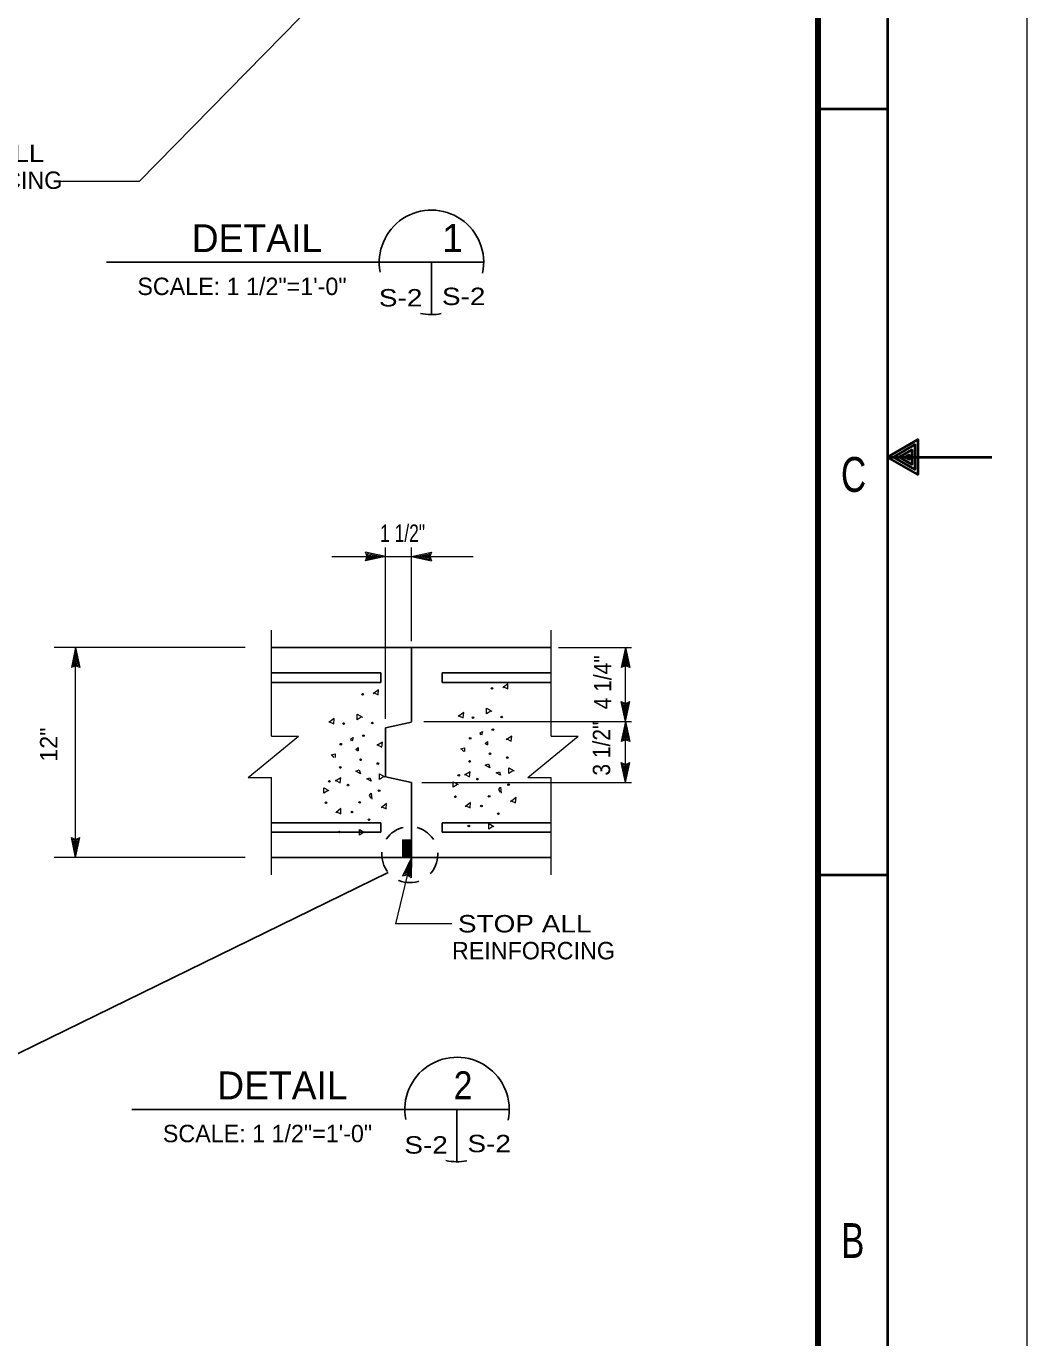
# Model space of a CAD drawing. Extents: x -22.3 to 19.7, y -11.8 to 18.2.
# Drawn here: x 12.51 to 19.69, y -3.16 to 6.25 of the extents above; entities that cross this region are included whole.
import ezdxf
from ezdxf.enums import TextEntityAlignment as Align

# ---------------------------------------------------------------- set-up
doc = ezdxf.new("R2010")
doc.units = 0
doc.header["$LTSCALE"] = 0.05
doc.linetypes.add('MEDIUM_DASHED', pattern=[4.5, 3, -1.5])
doc.layers.add('1', color=7, linetype='Continuous', lineweight=13)
doc.layers.add('2', color=7, linetype='Continuous', lineweight=13)

msp = doc.modelspace()

# ---------------------------------------------------------------- linework, layer by layer
at = {"layer": '1', "lineweight": 40}
for p, q in [((18.19058, 5.66031), (18.69058, 5.66031)), ((18.69058, 3.16031), (19.44058, 3.16031)), ((18.19058, 0.16031), (18.69058, 0.16031))]:
    msp.add_line(p, q, dxfattribs=at)
at = {"layer": '1', "lineweight": 25}
for p, q in [((13.08258, 4.55831), (15.79158, 4.55831)), ((15.41658, 4.55831), (15.41658, 4.18331)), ((14.26858, 1.79231), (16.27658, 1.79231)), ((15.27258, 1.26131), (15.27258, 1.79231)), ((15.05158, 1.61231), (14.27058, 1.61231)), ((15.05158, 1.54131), (15.05158, 1.61231)), ((15.49358, 1.61231), (16.27458, 1.61231)), ((15.49358, 1.54131), (15.49358, 1.61231)), ((15.05158, 1.54131), (14.27058, 1.54131)), ((15.49358, 1.54131), (16.27458, 1.54131)), ((15.27358, 1.25631), (15.08558, 1.21631)), ((15.08558, 0.86331), (15.08558, 1.21631)), ((15.27258, 0.82331), (15.08558, 0.86331)), ((15.27258, 0.28531), (15.27258, 0.82331)), ((15.05158, 0.53331), (14.26858, 0.53331)), ((15.05158, 0.46731), (15.05158, 0.53331)), ((15.49358, 0.53331), (16.27658, 0.53331)), ((15.49358, 0.46731), (15.49358, 0.53331)), ((15.05158, 0.46731), (14.26858, 0.46731)), ((15.21658, 0.28531), (15.21658, 0.41031)), ((15.22258, 0.28531), (15.22258, 0.41031)), ((15.22858, 0.28531), (15.22858, 0.41031)), ((15.23458, 0.28531), (15.23458, 0.41031)), ((15.23958, 0.28531), (15.23958, 0.41031)), ((15.24458, 0.28531), (15.24458, 0.41031)), ((15.25058, 0.28531), (15.25058, 0.41031)), ((15.25558, 0.28531), (15.25558, 0.41031)), ((15.26058, 0.28531), (15.26058, 0.41031)), ((15.26558, 0.28531), (15.26558, 0.41031)), ((15.26958, 0.28531), (15.26958, 0.41031)), ((15.49358, 0.46731), (16.27658, 0.46731)), ((14.26858, 0.28531), (16.27658, 0.28531)), ((13.26558, -1.52369), (15.97458, -1.52369)), ((15.59958, -1.52369), (15.59958, -1.89869))]:
    msp.add_line(p, q, dxfattribs=at)
at = {"layer": '1'}
for p, q in [((15.08558, 2.44531), (14.94158, 2.47631)), ((15.04858, 2.44531), (14.95458, 2.46531)), ((14.96358, 2.44531), (14.95458, 2.46531)), ((15.01258, 2.44531), (14.96758, 2.45431)), ((14.97158, 2.44531), (14.96758, 2.45431)), ((15.08558, 1.28031), (15.08558, 2.51131)), ((15.27258, 1.83731), (15.27258, 2.51131)), ((15.27358, 2.44531), (15.41758, 2.47631)), ((15.31058, 2.44531), (15.40458, 2.46531)), ((15.34658, 2.44531), (15.39158, 2.45531)), ((15.39158, 2.45531), (15.38758, 2.44531)), ((15.40458, 2.46531), (15.39558, 2.44531)), ((15.08558, 2.44531), (14.94158, 2.41431)), ((15.04858, 2.44531), (14.95458, 2.42531)), ((14.95458, 2.42531), (14.96358, 2.44531)), ((15.01258, 2.44531), (14.96758, 2.43531)), ((14.96758, 2.43531), (14.97158, 2.44531)), ((15.27358, 2.44531), (15.41758, 2.41431)), ((15.31058, 2.44531), (15.40458, 2.42531)), ((15.34658, 2.44531), (15.39158, 2.43631)), ((15.38758, 2.44531), (15.39158, 2.43631)), ((15.39558, 2.44531), (15.40458, 2.42531)), ((14.26858, 1.15731), (14.26858, 1.91831)), ((16.27658, 1.15731), (16.27658, 1.91831)), ((14.07758, 1.79231), (12.70658, 1.79231)), ((12.86158, 1.79231), (12.83058, 1.64831)), ((12.86158, 0.28531), (12.86158, 1.79231)), ((12.86158, 1.79231), (12.89258, 1.64831)), ((16.32858, 1.79231), (16.85258, 1.79231)), ((16.80958, 1.79231), (16.77858, 1.64831)), ((16.80958, 1.79231), (16.84058, 1.64831)), ((12.86158, 1.75531), (12.84158, 1.66131)), ((12.86158, 1.71931), (12.85258, 1.67431)), ((12.86158, 1.75531), (12.88158, 1.66131)), ((12.86158, 1.71931), (12.87158, 1.67431)), ((16.80958, 1.75531), (16.78958, 1.66131)), ((16.80958, 1.71931), (16.80058, 1.67431)), ((16.80958, 1.75531), (16.82958, 1.66131)), ((16.80958, 1.71931), (16.81958, 1.67431)), ((12.86158, 1.67031), (12.84158, 1.66131)), ((12.86158, 1.67831), (12.85258, 1.67431)), ((12.87158, 1.67431), (12.86158, 1.67831)), ((12.88158, 1.66131), (12.86158, 1.67031)), ((16.80958, 1.67031), (16.78958, 1.66131)), ((16.80958, 1.67831), (16.80058, 1.67431)), ((16.81958, 1.67431), (16.80958, 1.67831)), ((16.82958, 1.66131), (16.80958, 1.67031)), ((16.80958, 1.26131), (16.77858, 1.40531)), ((16.80958, 1.29831), (16.78958, 1.39231)), ((16.78958, 1.39231), (16.80958, 1.38331)), ((16.80958, 1.33431), (16.79958, 1.37931)), ((16.79958, 1.37931), (16.80958, 1.37531)), ((16.80958, 1.26131), (16.84058, 1.40531)), ((16.80958, 1.29831), (16.82958, 1.39231)), ((16.80958, 1.38331), (16.82958, 1.39231)), ((16.80958, 1.33431), (16.81858, 1.37931)), ((16.80958, 1.37531), (16.81858, 1.37931)), ((15.36158, 1.26131), (16.85258, 1.26131)), ((16.80958, 1.26131), (16.77858, 1.11731)), ((16.80958, 1.22431), (16.78958, 1.13031)), ((16.80958, 1.26131), (16.84058, 1.11731)), ((16.80958, 1.22431), (16.82958, 1.13031)), ((14.10058, 0.86031), (14.46158, 1.15731)), ((14.26858, 1.15731), (14.46158, 1.15731)), ((16.10858, 0.86031), (16.46958, 1.15731)), ((16.27658, 1.15731), (16.46958, 1.15731)), ((16.80958, 1.13931), (16.78958, 1.13031)), ((16.80958, 1.18831), (16.80058, 1.14331)), ((16.80958, 1.14731), (16.80058, 1.14331)), ((16.80958, 1.18831), (16.81958, 1.14331)), ((16.81958, 1.14331), (16.80958, 1.14731)), ((16.82958, 1.13031), (16.80958, 1.13931)), ((16.80958, 0.82331), (16.77858, 0.96731)), ((16.80958, 0.86031), (16.78958, 0.95431)), ((16.78958, 0.95431), (16.80958, 0.94531)), ((16.80958, 0.82331), (16.84058, 0.96731)), ((16.80958, 0.86031), (16.82958, 0.95431)), ((16.80958, 0.94531), (16.82958, 0.95431)), ((14.10058, 0.86031), (14.26858, 0.86031)), ((14.26858, 0.16131), (14.26858, 0.86031)), ((16.10858, 0.86031), (16.27658, 0.86031)), ((16.27658, 0.16131), (16.27658, 0.86031)), ((16.80958, 0.89631), (16.79958, 0.94131)), ((16.79958, 0.94131), (16.80958, 0.93731)), ((16.80958, 0.89631), (16.81858, 0.94131)), ((16.80958, 0.93731), (16.81858, 0.94131)), ((15.34658, 0.82331), (16.85258, 0.82331)), ((12.86158, 0.28531), (12.83058, 0.42931)), ((12.86158, 0.32231), (12.84158, 0.41631)), ((12.84158, 0.41631), (12.86158, 0.40731)), ((12.86158, 0.35831), (12.85158, 0.40331)), ((12.85158, 0.40331), (12.86158, 0.39931)), ((12.86158, 0.28531), (12.89258, 0.42931)), ((12.86158, 0.32231), (12.88158, 0.41631)), ((12.86158, 0.40731), (12.88158, 0.41631)), ((12.86158, 0.35831), (12.87058, 0.40331)), ((12.86158, 0.39931), (12.87058, 0.40331)), ((14.07758, 0.28531), (12.70658, 0.28531)), ((15.27258, 0.28531), (15.15858, -0.19069)), ((15.27258, 0.28531), (15.20858, 0.15231)), ((15.27258, 0.28531), (15.26958, 0.13831)), ((15.26358, 0.24931), (15.22258, 0.16231)), ((15.25558, 0.21431), (15.23658, 0.17231)), ((15.25558, 0.21431), (15.25458, 0.16831)), ((15.26358, 0.24931), (15.26158, 0.15331)), ((15.24458, 0.16631), (15.22258, 0.16231)), ((15.24558, 0.17431), (15.23658, 0.17231)), ((15.26158, 0.15331), (15.24458, 0.16631)), ((15.25458, 0.16831), (15.24558, 0.17431)), ((15.56158, -0.19069), (15.15858, -0.19069))]:
    msp.add_line(p, q, dxfattribs=at)
for points in [[(-22.30942, 18.16031), (19.69058, 18.16031), (19.69058, -11.83969)], [(14.60258, 6.44931), (13.31658, 5.13931), (12.74958, 5.13931)], [(14.94158, 2.41431), (14.95558, 2.44531), (14.94158, 2.47631)], [(15.41758, 2.47631), (15.40358, 2.44531), (15.41758, 2.41431)], [(14.70058, 2.44531), (15.08558, 2.44531), (15.27358, 2.44531), (15.71658, 2.44531)], [(16.80958, 0.82331), (16.80958, 1.26131), (16.80958, 1.79231)], [(12.89258, 1.64831), (12.86158, 1.66231), (12.83058, 1.64831)], [(16.84058, 1.64831), (16.80958, 1.66231), (16.77858, 1.64831)], [(16.77858, 1.40531), (16.80958, 1.39131), (16.84058, 1.40531)], [(16.84058, 1.11731), (16.80958, 1.13131), (16.77858, 1.11731)], [(16.77858, 0.96731), (16.80958, 0.95331), (16.84058, 0.96731)], [(12.83058, 0.42931), (12.86158, 0.41531), (12.89258, 0.42931)], [(15.26958, 0.13831), (15.24258, 0.15931), (15.20858, 0.15231)]]:
    msp.add_lwpolyline(points, dxfattribs=at)
at = {"layer": '1', "lineweight": 40}
for points in [[(-21.30942, -10.83969), (-21.30942, 17.16031), (18.69058, 17.16031), (18.69058, -10.83969)], [(18.69058, 3.16031), (18.90758, 3.28531), (18.90758, 3.03531)]]:
    msp.add_lwpolyline(points, close=True, dxfattribs=at)
at = {"layer": '1', "lineweight": 90}
msp.add_lwpolyline([(-19.80942, 16.66031), (18.19058, 16.66031), (18.19058, -10.33969), (-19.80942, -10.33969)], close=True, dxfattribs=at)
at = {"layer": '1', "lineweight": 40}
for points in [[(18.73358, 3.16031), (18.88658, 3.24931), (18.88658, 3.07131), (18.73458, 3.15931)], [(18.77358, 3.15931), (18.86558, 3.21331), (18.86558, 3.10731), (18.77258, 3.16131)], [(18.81558, 3.15931), (18.84558, 3.17731), (18.84558, 3.14331), (18.81858, 3.15831)]]:
    msp.add_lwpolyline(points, dxfattribs=at)
at = {"layer": '1', "lineweight": 25}
for points in [[(15.21058, 0.28531), (15.21058, 0.41031), (15.27258, 0.41031)], [(15.10558, 0.17831), (12.12358, -1.28069), (12.35458, -1.09869)]]:
    msp.add_lwpolyline(points, dxfattribs=at)
at = {"layer": '1', "linetype": 'MEDIUM_DASHED', "lineweight": 25}
msp.add_circle((15.26058, 0.30631), 0.20112, dxfattribs=at)
at = {"layer": '1', "lineweight": 25}
for centre, start, end in [((15.41658, 4.55831), 348.02387, 190.92017), ((15.41658, 4.55831), 257.81974, 280.71312), ((15.59958, -1.52369), 348.02387, 190.92017), ((15.59958, -1.52369), 257.81974, 280.71312)]:
    msp.add_arc(centre, 0.375, start, end, dxfattribs=at)
at = {"layer": '2'}
for p, q in [((15.64758, 1.04531), (15.62958, 1.06531)), ((14.71858, 1.00231), (14.70058, 1.02231))]:
    msp.add_line(p, q, dxfattribs=at)
for points in [[(15.92758, 1.51331), (15.96358, 1.49531), (15.96558, 1.53131), (15.92758, 1.50331)], [(14.99858, 1.47031), (15.03458, 1.45231), (15.03658, 1.48831), (14.99858, 1.46031)], [(15.60758, 1.30531), (15.64358, 1.28731), (15.64758, 1.32531), (15.60758, 1.29731)], [(15.84158, 1.33531), (15.81158, 1.31731), (15.81158, 1.35731), (15.84958, 1.33531)], [(14.67858, 1.26231), (14.71458, 1.24431), (14.71858, 1.28231), (14.67858, 1.25431)], [(14.91258, 1.29231), (14.88258, 1.27431), (14.88258, 1.31431), (14.92058, 1.29231)], [(14.84258, 1.12031), (14.83658, 1.13831), (14.85458, 1.14631), (14.84658, 1.12031)], [(15.77158, 1.16331), (15.76558, 1.18131), (15.78358, 1.18931), (15.77558, 1.16331)], [(15.95358, 1.13931), (15.98958, 1.12131), (15.99358, 1.15731), (15.95358, 1.13131)], [(14.89058, 1.04831), (14.87258, 1.06031), (14.89058, 1.07431), (14.89058, 1.05231)], [(15.02458, 1.09631), (15.06058, 1.07831), (15.06458, 1.11431), (15.02458, 1.08831)], [(15.62558, 1.06531), (15.65358, 1.07331), (15.65358, 1.04531)], [(15.81958, 1.09131), (15.80158, 1.10331), (15.81958, 1.11731), (15.81958, 1.09531)], [(14.69658, 1.02231), (14.72458, 1.03031), (14.72458, 1.00231)], [(14.72458, 0.84031), (14.76058, 0.82231), (14.76458, 0.85831), (14.72458, 0.83231)], [(15.07258, 0.86431), (15.04258, 0.84631), (15.04258, 0.88631), (15.08058, 0.86431)], [(15.65358, 0.88331), (15.68958, 0.86531), (15.69358, 0.90131), (15.65358, 0.87531)], [(16.00158, 0.90731), (15.97158, 0.88931), (15.97158, 0.92931), (16.00958, 0.90731)], [(14.67458, 0.76631), (14.64258, 0.74831), (14.64258, 0.78631), (14.67858, 0.76631)], [(15.60358, 0.80931), (15.57158, 0.79131), (15.57158, 0.82931), (15.60758, 0.80931)], [(15.91158, 0.75531), (15.89958, 0.77331), (15.91158, 0.79131), (15.91758, 0.74731)], [(14.98258, 0.71231), (14.97058, 0.73031), (14.98258, 0.74831), (14.98858, 0.70431)], [(15.05458, 0.65231), (15.09058, 0.63431), (15.09458, 0.67231), (15.05458, 0.64231)], [(15.65758, 0.65931), (15.69358, 0.64131), (15.69558, 0.67931), (15.65758, 0.64931)], [(15.98358, 0.69531), (16.01958, 0.67731), (16.02358, 0.71531), (15.98358, 0.68531)], [(14.72858, 0.61631), (14.76458, 0.59831), (14.76658, 0.63631), (14.72858, 0.60631)], [(14.92858, 0.46431), (14.89858, 0.44631), (14.89858, 0.48631), (14.93458, 0.46431)], [(15.85758, 0.50731), (15.82758, 0.48931), (15.82758, 0.52931), (15.86358, 0.50731)]]:
    msp.add_lwpolyline(points, dxfattribs=at)
for points in [[(15.83558, 0.92931), (15.80158, 0.94731), (15.82558, 0.95731)], [(14.90658, 0.88631), (14.87258, 0.90431), (14.89658, 0.91431)], [(14.98258, 0.83231), (14.95258, 0.85031), (14.97458, 0.85831)], [(15.91158, 0.87531), (15.88158, 0.89331), (15.90358, 0.90131)]]:
    msp.add_lwpolyline(points, close=True, dxfattribs=at)
for centre in [(14.92173, 1.45671), (15.85073, 1.49971), (14.78583, 1.24701), (14.99193, 1.25061), (15.71483, 1.29001), (15.92093, 1.29361), (14.92803, 1.15971), (15.69413, 1.14151), (15.85703, 1.20271), (14.76513, 1.09851), (15.83633, 1.02991), (14.90733, 0.98691), (15.03153, 0.95991), (15.69053, 0.97501), (15.96053, 1.00291), (14.76153, 0.93201), (15.61223, 0.87511), (15.74543, 0.84811), (14.68323, 0.83211), (14.81643, 0.80511), (15.04053, 0.76551), (15.96953, 0.80851), (14.65893, 0.67821), (14.90103, 0.68091), (15.58793, 0.72121), (15.77513, 0.65461), (15.83003, 0.72391), (14.84613, 0.61161), (15.89663, 0.59971), (14.75523, 0.46851), (14.96763, 0.55671), (15.68423, 0.51151)]:
    msp.add_circle(centre, 0.00585, dxfattribs=at)

# ---------------------------------------------------------------- texts
at = {"layer": '1'}
for s, height, width, p in [('STOP ALL', 0.125, 1.2, (12.15758, 5.27831)), ('S-2', 0.125, 1.2, (15.19458, 4.24131)), ('S-2', 0.125, 1.2, (15.64758, 4.25131)), ('C', 0.25, 0.75, (18.44708, 2.91031)), ('1 1/2"', 0.125, 0.75, (15.20858, 2.55131)), ('STOP ALL', 0.125, 1.2, (16.08558, -0.25269)), ('2', 0.2, 0.9, (15.64308, -1.44969)), ('S-2', 0.125, 1.2, (15.37758, -1.84069)), ('S-2', 0.125, 1.2, (15.83058, -1.83069)), ('B', 0.25, 0.75, (18.44108, -2.58969))]:
    msp.add_text(s, height=height, dxfattribs=dict(at, width=width)).set_placement(p, align=Align.CENTER)
for p in [(12.76558, 5.08531), (16.73358, -0.44569)]:
    msp.add_text('REINFORCING', height=0.125, dxfattribs=at).set_placement(p, align=Align.RIGHT)
for s, p in [('DETAIL', (14.16308, 4.63131)), ('1', (15.5676, 4.63231)), ('DETAIL', (14.34608, -1.45069))]:
    msp.add_text(s, height=0.2, dxfattribs=at).set_placement(p, align=Align.CENTER)
for p in [(13.30458, 4.32331), (13.48758, -1.75869)]:
    msp.add_text('SCALE: 1 1/2"=1\'-0"', height=0.125, dxfattribs=at).set_placement(p)
at = {"layer": '1', "width": 0.9}
for s, p in [('4 1/4"', (16.70758, 1.54331)), ('3 1/2"', (16.69958, 1.06731))]:
    msp.add_text(s, height=0.125, rotation=90, dxfattribs=at).set_placement(p, align=Align.CENTER)
at = {"layer": '1'}
msp.add_text('12"', height=0.125, rotation=90, dxfattribs=at).set_placement((12.73058, 1.09581), align=Align.CENTER)

doc.saveas('drawing.dxf')
